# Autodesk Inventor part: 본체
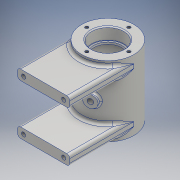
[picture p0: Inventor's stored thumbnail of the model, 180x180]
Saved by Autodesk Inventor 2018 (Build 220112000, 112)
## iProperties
Created: 2020-07
Part Number: 본체
Material: 알루미늄 6061
Document SubType Name: Modeling
Designer: home
Density: 2.7 g/cm^3
Appearance: 알루미늄 - 평지
Mass: 305.802 g
Surface Area: 360.882 cm^2
Volume: 113.26 cm^3
Author: home
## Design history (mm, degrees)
sketch "스케치1"
  geometry: L1 (0, 54.042)-(0, -37.312); L2 (16, 35)-(16, 23); L3 (16, 23)-(14, 23); L4 (14, 23)-(14, 21); L5 (14, 21)-(21, 21); L6 (21, 21)-(21, -21); L7 (21, -21)-(14, -21); L8 (14, -21)-(14, -23); L9 (16, -35)-(26, -35); L10 (26, -35)-(26, 35); L11 (26, 35)-(16, 35); L12 (14, -23)-(16, -23); L13 (16, -23)-(16, -35); 1 further point
  constraints: 26 end point, 8 perpendicular, 4 point on line, 2 vertical, 1 horizontal
  dimensions: "d0" = 52 diameter of L10 L1; "d1" = 32 diameter of L13 L1; "d2" = 42 diameter of L6 L1; "d3" = 28 diameter of L8 L1; "d7" = 12 distance of L2.start L2.end; "d8" = 12 distance of L12.end L9.start; "d9" = 70 distance of L9.end L10.end; "d10" = 35 vertical distance of point (0, 0) L10.end; "d12" = 42 distance of L5.end L6.end; "d13" = 2 distance of L3.end L4.end; "d15" = 19.04172 distance from line of L1.start L11; "d16" = 72.31179 distance from line of L1.end L11
revolve "회전1" sketch "스케치1" stored, may be unused: angle "d14" = 90 deg
node "작업 평면1"
sketch "스케치2"
  geometry: L1 (-26, 30)-(26, 30); L2 (26, 30)-(26, 20); L3 (26, 20)-(-26, 20); L4 (-26, 20)-(-26, 30); L5 (-26, -20)-(26, -20); L6 (26, -20)-(26, -30); L7 (26, -30)-(-26, -30); L8 (-26, -30)-(-26, -20); 1 further point
  constraints: 16 end point, 4 parallel, 2 horizontal, 2 perpendicular
  dimensions: "d18" = 10 distance of L3.end L1.start; "d21" = 10 distance of L7.end L5.start; "d24" = 30 distance from line of L1 point (0, 0); "d25" = 30 distance from line of L7 point (0, 0); "d28" = 52 distance of L1.start L1.end; "d29" = 52 distance of L6.end L7.end; "d30" = 26 distance from line of point (0, 0) L4; "d31" = 26 distance from line of L8 point (0, 0)
extrude "돌출1" join sketch "스케치2" stored distance "d26" = 10; taper "d27" = 0 deg
sketch "스케치3"
  geometry: L1 (26, 30)-(-26, 30) reference; 3 further points
  constraints: 1 horizontal alignment
  dimensions: "d32" = 5 distance from line of L1 point (20, 25); "d33" = 20 horizontal distance of point (0, 0) point (20, 25); "d35" = 20 horizontal distance of point (0, 0) point (-20, 25)
hole "구멍1" sketch "스케치3" at (20, 25), (-20, 25) diameter "d36" = 4.134; stored, may be unused: countersink angle "d40" = 90 deg, drill point angle "d42" = 118 deg; dims "d37" = 8, "d38" = 4, "d39" = 2, "d41" = 10
node "작업 평면2"
sketch "스케치4"
  geometry: C1 r 5 at (0, 0); 1 further point
  constraints: 1 centre point, 1 coincident
  dimensions: "d44" = 10 diameter of C1
extrude "돌출2" join sketch "스케치4" stored distance "d45" = 10; taper "d46" = 0 deg
sketch "스케치5"
  geometry: C1 r 5 at (0, 0) reference; 1 further point
hole "구멍2" sketch "스케치5" at (0, 0) diameter "d50" = 5.188; stored, may be unused: countersink angle "d54" = 90 deg, drill point angle "d56" = 118 deg; dims "d51" = 12, "d52" = 4, "d53" = 2, "d55" = 16
sketch "스케치6"
  geometry: C1 r 2.594 at (0, 0) reference; C2 r 6 at (0, 0); 1 further point
  constraints: 1 centre point, 1 coincident
  dimensions: "d60" = 12 diameter of C2
extrude "돌출3" join sketch "스케치6" stored distance "d61" = 10; taper "d62" = 0 deg; dims "d0" = 52, "d1" = 32, "d2" = 42, "d3" = 28, "d7" = 12, "d8" = 12, "d9" = 70, "d10" = 35, "d12" = 42, "d13" = 2, "d15" = 19.04172, "d16" = 72.31179
sketch "스케치7"
  geometry: 2 further points
  constraints: 1 vertical alignment
  dimensions: "d63" = 21 distance of point (0, 0) point (0, 21)
hole "구멍3" sketch "스케치7" at (0, 21) diameter "d64" = 3.242; stored, may be unused: countersink angle "d68" = 90 deg, drill point angle "d70" = 118 deg; dims "d65" = 8, "d66" = 4, "d67" = 2, "d69" = 10
sketch "스케치8"
  geometry: L1 (-5, 90)-(-5, 38) reference; L2 (65, 90)-(-5, 90) reference; 2 further points
  constraints: 1 other
  dimensions: "d74" = 35 distance from line of L1 point (30, 66); "d75" = 24 distance from line of L2 point (30, 66)
feature "엠보싱1" sketch "스케치8" dims "d0" = 52, "d1" = 32, "d2" = 42, "d3" = 28, "d7" = 12, "d8" = 12, "d9" = 70, "d10" = 35, "d12" = 42, "d13" = 2, "d15" = 19.04172, "d16" = 72.31179, "d76" = 0.5, "d77" = 0
fillet "모깎기1" dims "d78" = 0.3, "d79" = 3, "d80" = 2
fillet "모깎기2" dims "d81" = 2
chamfer "모따기1" distance "d82" = 1; stored, may be unused: second distance "d83" = 2, angle "d84" = 45 deg
node "솔리드1"
mirror "미러1"
pattern_circular "원형 패턴2" dims angle "d58" = 160 deg
pattern_circular "원형 패턴3" dims angle "d72" = 360 deg
mirror "미러2"
other parameters: "d17" = -64, "d43" = 29
